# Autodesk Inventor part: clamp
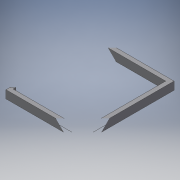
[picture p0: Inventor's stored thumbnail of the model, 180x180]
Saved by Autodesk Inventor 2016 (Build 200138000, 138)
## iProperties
Created: 2016-12
Part Number: clamp
Material: Generic
Document SubType Name: Modeling
Designer: jose
Density: 1 g/cm^3
Appearance: Default
Author: jose
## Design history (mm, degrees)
sketch "Sketch1"
  geometry: L1 (0, 0)-(55.296, 0); L2 (55.296, 0)-(55.296, 6.096); L3 (55.296, 6.096)-(0, 6.096); L4 (0, 6.096)-(0, 0)
  constraints: 8 end point, 2 parallel, 1 horizontal, 1 perpendicular
  dimensions: "d0" = 6.096 distance of L3.end L1.start; "d1" = 55.2958 distance of L2.end L3.end
extrude "Extrusion1" new body sketch "Sketch1" distance "d2" = 3.175; taper "d3" = 0 deg
sketch "Sketch2"
  geometry: L1 (0, 0)-(-69.85, 0); L2 (-69.85, 0)-(-69.85, 6.096); L3 (-69.85, 6.096)-(0, 6.096); L4 (0, 6.096)-(0, 0); L5 (0, 6.096)-(-3.175, 6.096) reference
  constraints: 8 end point, 2 parallel, 1 collinear, 1 horizontal, 1 perpendicular
  dimensions: "d4" = 69.85 distance of L1.start L1.end
extrude "Extrusion2" join sketch "Sketch2" distance "d5" = 3.175; taper "d6" = 0 deg
sketch "Sketch3"
  geometry: L1 (69.85, 0)-(0, 0) reference; L2 (69.85, 6.096)-(66.675, 6.096); L3 (66.675, 6.096)-(66.675, 0); L4 (66.675, 0)-(69.85, 0); L5 (69.85, 0)-(69.85, 6.096); L6 (69.85, 6.096)-(3.175, 6.096) reference; L7 (69.85, 0)-(69.85, 6.096) reference
  constraints: 8 end point, 2 collinear, 2 parallel, 1 horizontal, 1 perpendicular, 1 point on line
  dimensions: "d7" = 3.175 distance of L2.start L2.end
extrude "Extrusion3" join sketch "Sketch3" stored distance "d8" = 3.175; taper "d9" = 0 deg
sketch "Sketch4"
  geometry: L1 (0, -3.175)-(2.286, -5.156); L2 (2.286, -5.156)-(2.286, -3.175); L3 (2.286, -3.175)-(0, -3.175); L4 (0, -66.675)-(2.286, -64.694); L5 (2.286, -64.694)-(2.286, -66.675); L6 (55.296, -66.675)-(0, -66.675) reference; L7 (0, -69.85)-(0, -66.675) reference; L8 (0, -66.675)-(2.286, -66.675); 1 further point
  constraints: 12 end point, 2 collinear, 2 perpendicular, 2 vertical, 1 point on line
  dimensions: "d10" = 1.9812 distance of L1.end L2.end; "d11" = 2.286 distance from line of L1.start L2
extrude "Extrusion4" join sketch "Sketch4" stored distance "d12" = 3.175; taper "d13" = 0 deg
body "Solid1"
